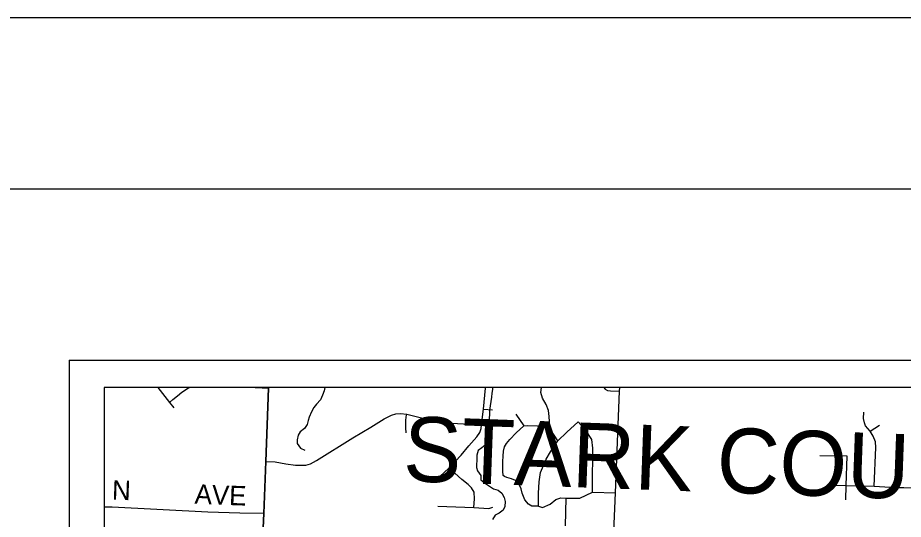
# Model space of a CAD drawing. Extents: x 0 to 34, y 0 to 22.
# Drawn here: x 2.584 to 5.169, y 20.536 to 22 of the extents above; entities that cross this region are included whole.
import ezdxf

# ---------------------------------------------------------------- set-up
doc = ezdxf.new("R2010")
doc.units = 0
for name, color, linetype in [('GM_X_Corporation', 7, 'Continuous'), ('GM_X_County_Road', 7, 'Continuous'), ('GM_X_County_Text', 7, 'Continuous'), ('GM_X_Minor_River', 7, 'Continuous'), ('GM_X_Township_Road', 7, 'Continuous'), ('GM_X_Township_Road_Text', 7, 'Continuous'), ('SH_Border', 7, 'Continuous'), ('SH_Cut_Line', 7, 'Continuous'), ('SH_Data', 7, 'Continuous')]:
    doc.layers.add(name, color=color, linetype=linetype)

msp = doc.modelspace()

# ---------------------------------------------------------------- linework, layer by layer
at = {"layer": 'GM_X_Corporation'}
for points in [[(7.1023, 20.9204), (2.837, 20.9204), (2.837, 14.1204), (9.637, 14.1204), (9.637, 20.9204), (9.4036, 20.9204), (9.4022, 20.8667), (9.2273, 20.8723), (9.1354, 20.8749), (9.124, 20.8753), (8.9858, 20.878), (8.9676, 20.8785), (8.8663, 20.881), (8.6259, 20.8892), (8.5535, 20.8914), (8.5421, 20.8915), (8.4667, 20.8934), (8.0602, 20.9055), (7.9522, 20.9084), (7.1104, 20.9188)], [(3.3169, 20.9204), (2.837, 20.9204), (2.837, 14.9888), (3.0725, 14.9816), (3.0874, 15.351), (3.0879, 15.3623), (3.0883, 15.3712), (3.1072, 15.7483), (3.1177, 16.2414), (3.14, 16.6736), (3.1852, 17.7826), (3.1864, 17.8248), (3.233, 19.0394), (3.2586, 19.6098), (3.2623, 19.6596), (3.2721, 19.8755), (3.2728, 19.892), (3.2744, 19.9301), (3.2774, 20.0014), (3.2794, 20.0412), (3.3026, 20.5526), (3.3089, 20.7046), (3.3168, 20.9187)]]:
    msp.add_lwpolyline(points, close=True, dxfattribs=at)
msp.add_lwpolyline([(7.1023, 20.9204), (3.3169, 20.9204), (3.3168, 20.9187), (3.3089, 20.7046), (3.3026, 20.5526), (3.2794, 20.0412), (3.2774, 20.0014), (3.2744, 19.9301), (3.2728, 19.892), (3.2721, 19.8755), (3.2623, 19.6596), (3.2586, 19.6098), (3.233, 19.0394), (3.1864, 17.8248)], dxfattribs=at)
at = {"layer": 'GM_X_County_Road'}
msp.add_lwpolyline([(3.2688, 19.5867), (3.268, 19.5898), (3.2655, 19.6012), (3.2642, 19.6089), (3.2628, 19.6257), (3.2623, 19.642), (3.2626, 19.659), (3.2723, 19.875), (3.273, 19.8915), (3.2746, 19.9296), (3.2776, 20.0009), (3.2796, 20.0406), (3.2855, 20.1153), (3.288, 20.1827), (3.29, 20.2522), (3.2943, 20.3595), (3.3028, 20.552), (3.3091, 20.704), (3.317, 20.9182), (3.3171, 20.9204)], dxfattribs=at)
at = {"layer": 'GM_X_Minor_River'}
for points in [[(3.4811, 20.9204), (3.4788, 20.9109), (3.4744, 20.8983), (3.4681, 20.8846), (3.4568, 20.8715), (3.4486, 20.8616), (3.4422, 20.8489), (3.4348, 20.8337), (3.4319, 20.8241), (3.429, 20.8127), (3.4211, 20.8005), (3.4091, 20.7905), (3.4031, 20.7809), (3.3998, 20.7672), (3.3999, 20.7565), (3.41, 20.7434), (3.4222, 20.737)], [(3.97, 20.9204), (3.9697, 20.9147), (3.9686, 20.9041), (3.9669, 20.8923), (3.9651, 20.879), (3.963, 20.8664), (3.9612, 20.8546), (3.961, 20.8421), (3.9603, 20.8299), (3.9593, 20.8185), (3.9591, 20.8082), (3.9546, 20.7987), (3.9532, 20.7854), (3.953, 20.7736), (3.9516, 20.7614), (3.9483, 20.7515), (3.9385, 20.7438), (3.9279, 20.7368), (3.9243, 20.7224), (3.9241, 20.7064), (3.9238, 20.6961), (3.9232, 20.6866), (3.9259, 20.6768), (3.9356, 20.6632), (3.9361, 20.6503), (3.9495, 20.6402), (3.9617, 20.632), (3.9728, 20.6249), (3.9862, 20.6204), (3.9969, 20.6114), (4.0039, 20.5994), (4.0071, 20.5872), (4.0061, 20.5732), (4.0013, 20.5625), (3.9896, 20.5536), (3.9779, 20.5474), (3.97, 20.5348)]]:
    msp.add_lwpolyline(points, dxfattribs=at)
at = {"layer": 'GM_X_Township_Road'}
for p, q in [((3.2778, 20.9204), (3.317, 20.9182)), ((3.9438, 20.8575), (3.9697, 20.855)), ((5.0724, 20.7927), (5.0995, 20.8102)), ((4.1827, 20.5162), (4.1855, 20.5973))]:
    msp.add_line(p, q, dxfattribs=at)
for points in [[(2.9932, 20.9204), (2.9999, 20.9113), (3.0276, 20.8768), (3.0397, 20.8609)], [(3.0276, 20.8768), (3.0376, 20.8849), (3.0512, 20.8964), (3.063, 20.9063), (3.0798, 20.9172), (3.0859, 20.9204)], [(3.8167, 20.6603), (3.8422, 20.6852), (3.8785, 20.7227), (3.9014, 20.7502), (3.9246, 20.7767), (3.9329, 20.7891), (3.9373, 20.8008), (3.9383, 20.8118), (3.9438, 20.8575), (3.9492, 20.9185), (3.9488, 20.9204)], [(4.1612, 20.7648), (4.1391, 20.7974), (4.1374, 20.8062), (4.1351, 20.8359), (4.1337, 20.853), (4.1269, 20.871), (4.1162, 20.8896), (4.1109, 20.9057), (4.1135, 20.9204)], [(4.2439, 18.4919), (4.2655, 18.9966), (4.2737, 19.2276), (4.2759, 19.2794), (4.2802, 19.3808), (4.2827, 19.4257), (4.2875, 19.5306), (4.2904, 19.6566), (4.2961, 19.799), (4.2987, 19.8835), (4.3055, 20.0023), (4.3079, 20.0845), (4.3139, 20.2312), (4.3194, 20.3462), (4.3214, 20.4305), (4.3286, 20.6129), (4.3409, 20.9092), (4.3413, 20.9204)], [(4.2954, 20.9204), (4.2993, 20.9155), (4.3055, 20.9118), (4.3144, 20.9103), (4.3409, 20.9092)], [(3.3091, 20.704), (3.3359, 20.7029), (3.3668, 20.6975), (3.3952, 20.6939), (3.4166, 20.6934), (3.4257, 20.6939), (3.4319, 20.6954), (3.4391, 20.6971), (3.4563, 20.7074), (3.5626, 20.7735), (3.6146, 20.8042), (3.6542, 20.8285), (3.6755, 20.8393), (3.6884, 20.8433), (3.7014, 20.8441), (3.72, 20.842), (3.751, 20.8349), (3.7747, 20.8289), (3.7875, 20.8262), (3.8051, 20.8245), (3.8211, 20.8242), (3.8354, 20.8217), (3.8503, 20.8165), (3.9383, 20.8118)], [(3.7186, 20.7884), (3.718, 20.7927), (3.7175, 20.7974), (3.7171, 20.8014), (3.7167, 20.8054), (3.7168, 20.8109), (3.7169, 20.8164), (3.717, 20.8202), (3.7173, 20.824), (3.7175, 20.8272), (3.7177, 20.8304), (3.7184, 20.8343), (3.719, 20.8383), (3.72, 20.842)], [(4.0385, 20.8426), (4.0615, 20.8087), (4.0712, 20.8093), (4.1013, 20.8081), (4.1374, 20.8062)], [(5.0844, 20.6321), (5.0885, 20.7455), (5.0882, 20.762), (5.0807, 20.7778), (5.0724, 20.7927), (5.0582, 20.8085), (5.056, 20.8167), (5.0526, 20.8298), (5.0537, 20.8485)], [(4.1043, 20.5737), (4.0847, 20.5742), (4.0754, 20.5797), (4.0642, 20.5924), (4.057, 20.6117), (4.0537, 20.6245), (4.0474, 20.6388), (4.0422, 20.6469), (4.0251, 20.6534), (4.0115, 20.658), (4.0056, 20.6601), (4.0012, 20.6633), (4.0003, 20.6763), (4.0006, 20.704), (4.0009, 20.72), (4.0022, 20.7347), (4.0056, 20.7468), (4.0112, 20.7564), (4.0211, 20.7689), (4.0391, 20.7878), (4.0615, 20.8087)], [(4.1043, 20.5737), (4.1048, 20.6119), (4.1067, 20.6449), (4.1098, 20.6723), (4.1272, 20.7108), (4.1396, 20.7326), (4.1612, 20.7648), (4.1869, 20.7903), (4.2198, 20.8202)], [(4.2618, 20.6144), (4.2622, 20.6747), (4.2629, 20.7005), (4.2629, 20.714), (4.2626, 20.7429), (4.2601, 20.7681), (4.2437, 20.7937), (4.2198, 20.8202)], [(5.0009, 20.5924), (5.0023, 20.634), (5.0051, 20.7197), (4.925, 20.7204)], [(3.9154, 20.5695), (3.9172, 20.595), (3.9163, 20.6146), (3.9091, 20.6269), (3.8988, 20.6368), (3.8808, 20.6519), (3.8606, 20.6703), (3.8422, 20.6852)], [(4.9498, 20.6352), (5.0023, 20.634), (5.0844, 20.6321), (5.1463, 20.6285), (5.1703, 20.6288), (5.2189, 20.627), (5.2369, 20.6224), (5.2481, 20.6139), (5.2594, 20.6061), (5.2706, 20.5993), (5.2826, 20.5949), (5.2934, 20.5941), (5.3155, 20.5924), (5.341, 20.5916)], [(4.1043, 20.5737), (4.1161, 20.5701), (4.1382, 20.5799), (4.1547, 20.5933), (4.1699, 20.5983), (4.1855, 20.5973), (4.2251, 20.597), (4.2618, 20.6144), (4.3286, 20.6129)], [(3.8103, 20.5739), (3.9154, 20.5695), (3.9595, 20.5675), (3.9711, 20.5712)], [(3.3028, 20.552), (3.2323, 20.5531), (3.139, 20.5568), (2.8599, 20.5705), (2.837, 20.5713)]]:
    msp.add_lwpolyline(points, dxfattribs=at)
at = {"layer": 'SH_Border'}
msp.add_lwpolyline([(1.5, 21.5), (33.5, 21.5), (33.5, 0.5), (1.5, 0.5)], close=True, dxfattribs=at)
at = {"layer": 'SH_Cut_Line'}
msp.add_lwpolyline([(0, 0), (34, 0), (34, 22), (0, 22)], close=True, dxfattribs=at)
at = {"layer": 'SH_Data'}
for q in [(9.7349, 21.0001), (2.7349, 14.0001)]:
    msp.add_line((2.7349, 21.0001), q, dxfattribs=at)

# ---------------------------------------------------------------- texts
at = {"layer": 'GM_X_County_Text'}
msp.add_text('STARK COUNTY', height=0.189394, rotation=357.9394, dxfattribs=at).set_placement((3.7076, 20.6474))
at = {"layer": 'GM_X_Township_Road_Text'}
for s, rotation, p in [('N', 357.9669, (2.8589, 20.593)), ('A', 357.4967, (3.1, 20.5815)), ('V', 357.5061, (3.15, 20.5793)), ('E', 358.0904, (3.2006, 20.5771))]:
    msp.add_text(s, height=0.0568, rotation=rotation, dxfattribs=at).set_placement(p)

doc.saveas('drawing.dxf')
